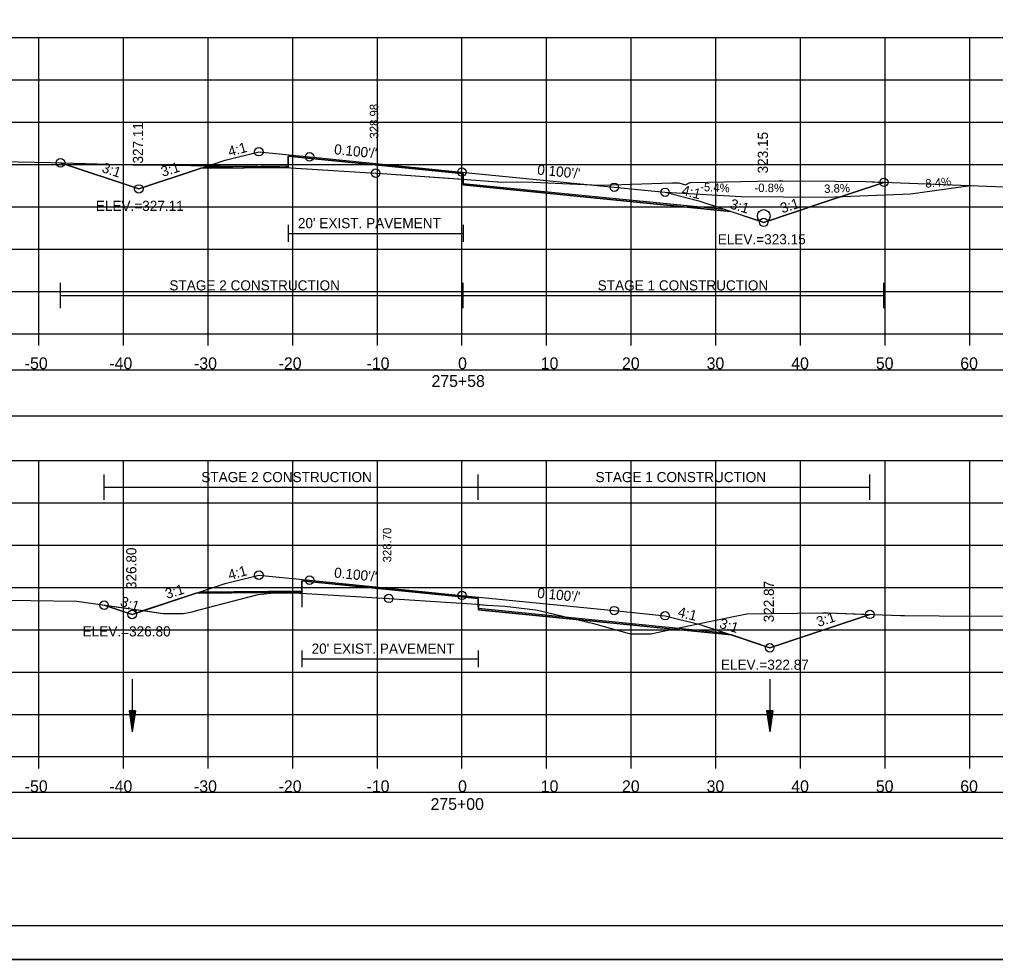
# Model space of a CAD drawing. Extents: x 1376273 to 1384221, y 378927 to 384592.
# Drawn here: x 1380139.4 to 1380254.7, y 383738.6 to 383849.7 of the extents above; entities that cross this region are included whole.
import ezdxf

# ---------------------------------------------------------------- set-up
doc = ezdxf.new("R2010")
doc.units = 0
for name, color, linetype in [('R_Alt Surface', 7, 'Continuous'), ('R_Alt Surface Annot', 7, 'Continuous'), ('R_Axis', 7, 'Continuous'), ('R_Axis Annot', 7, 'Continuous'), ('R_Border', 7, 'Continuous'), ('R_Border Notes', 7, 'Continuous'), ('R_Contours', 7, 'Continuous'), ('R_Dimension', 7, 'Continuous'), ('R_Drive', 7, 'Continuous'), ('R_Exist Surface', 7, 'Continuous'), ('R_Fin Surface', 7, 'Continuous'), ('R_Grid', 7, 'Continuous'), ('R_No Plot', 7, 'Continuous'), ('R_Water', 7, 'Continuous'), ('R_Xsect Elev', 7, 'Continuous'), ('R_Xsect Slope', 7, 'Continuous'), ('T_Detection Zones', 7, 'Continuous')]:
    doc.layers.add(name, color=color, linetype=linetype)

msp = doc.modelspace()

# ---------------------------------------------------------------- linework, layer by layer
at = {"layer": 'R_Alt Surface'}
for points in [[(1380161.32, 383832.29), (1380171.12, 383832.39), (1380171.13, 383833.55), (1380191.66, 383831.5), (1380191.8, 383831.48), (1380191.81, 383830.32), (1380222.68, 383827.26)], [(1380171.13, 383825.42), (1380171.13, 383823.42)], [(1380191.8, 383825.42), (1380191.8, 383823.42)], [(1380171.13, 383824.42), (1380191.8, 383824.42)], [(1380160.77, 383782.06), (1380172.73, 383782.18), (1380172.74, 383783.35), (1380191.66, 383781.46), (1380193.59, 383781.26), (1380193.6, 383780.1), (1380222.79, 383777.18)], [(1380172.74, 383775.12), (1380172.74, 383773.12)], [(1380193.59, 383775.12), (1380193.59, 383773.12)], [(1380172.74, 383774.12), (1380193.59, 383774.12)]]:
    msp.add_lwpolyline(points, dxfattribs=at)
at = {"layer": 'R_Alt Surface Annot'}
msp.add_circle((1380227.31, 383826.47), 0.75, dxfattribs=at)
at = {"layer": 'R_Axis'}
for p, q in [((1380041.66, 383812.56), (1380341.66, 383812.56)), ((1380141.66, 383811.16), (1380141.66, 383812.56)), ((1380151.66, 383811.16), (1380151.66, 383812.56)), ((1380161.66, 383811.16), (1380161.66, 383812.56)), ((1380171.66, 383811.16), (1380171.66, 383812.56)), ((1380181.66, 383811.16), (1380181.66, 383812.56)), ((1380191.66, 383811.16), (1380191.66, 383812.56)), ((1380201.66, 383811.16), (1380201.66, 383812.56)), ((1380211.66, 383811.16), (1380211.66, 383812.56)), ((1380221.66, 383811.16), (1380221.66, 383812.56)), ((1380231.66, 383811.16), (1380231.66, 383812.56)), ((1380241.66, 383811.16), (1380241.66, 383812.56)), ((1380251.66, 383811.16), (1380251.66, 383812.56)), ((1380041.66, 383762.56), (1380341.66, 383762.56)), ((1380141.66, 383761.16), (1380141.66, 383762.56)), ((1380151.66, 383761.16), (1380151.66, 383762.56)), ((1380161.66, 383761.16), (1380161.66, 383762.56)), ((1380171.66, 383761.16), (1380171.66, 383762.56)), ((1380181.66, 383761.16), (1380181.66, 383762.56)), ((1380191.66, 383761.16), (1380191.66, 383762.56)), ((1380201.66, 383761.16), (1380201.66, 383762.56)), ((1380211.66, 383761.16), (1380211.66, 383762.56)), ((1380221.66, 383761.16), (1380221.66, 383762.56)), ((1380231.66, 383761.16), (1380231.66, 383762.56)), ((1380241.66, 383761.16), (1380241.66, 383762.56)), ((1380251.66, 383761.16), (1380251.66, 383762.56))]:
    msp.add_line(p, q, dxfattribs=at)
at = {"layer": 'R_Axis Annot'}
for points in [[(1380040.81, 383802.85), (1380342.5, 383802.85), (1380342.5, 383808.26), (1380040.81, 383808.26)], [(1380040.81, 383752.92), (1380342.5, 383752.92), (1380342.5, 383758.33), (1380040.81, 383758.33)]]:
    msp.add_lwpolyline(points, close=True, dxfattribs=at)
at = {"layer": 'R_Border'}
msp.add_line((1380349.84, 383742.56), (1380033.66, 383742.56), dxfattribs=at)
at = {"layer": 'R_Contours'}
for p, q in [((1380160.25, 383781.89), (1380154.04, 383779.82)), ((1380172.73, 383782.01), (1380160.25, 383781.89)), ((1380172.73, 383782.01), (1380172.73, 383780.22)), ((1380172.73, 383782.01), (1380172.73, 383781.88)), ((1380172.73, 383781.88), (1380172.73, 383782.01)), ((1380193.59, 383780.55), (1380193.59, 383781.26))]:
    msp.add_line(p, q, dxfattribs=at)
for points in [[(1380191.8, 383830.81), (1380192.8, 383830.74), (1380195.83, 383830.5), (1380195.95, 383830.49), (1380196.24, 383830.47), (1380198.2, 383830.49), (1380200.07, 383830.47), (1380207.9, 383830.1), (1380208.14, 383830.1), (1380216.47, 383830.39), (1380217.28, 383830.4), (1380218.09, 383830.17), (1380218.6, 383830.43), (1380218.76, 383830.44), (1380226.57, 383830.6), (1380229.07, 383830.61), (1380229.57, 383830.64), (1380235.79, 383830.59), (1380239.39, 383830.53), (1380241.52, 383830.45), (1380234.24, 383828.03), (1380227.31, 383825.72), (1380223.39, 383827.02), (1380191.81, 383830.15)], [(1380193.59, 383780.55), (1380194.59, 383780.48), (1380196.73, 383780.34), (1380197.04, 383780.31), (1380197.4, 383780.27), (1380200.36, 383779.91), (1380200.93, 383779.78), (1380205.23, 383778.77), (1380193.6, 383779.93)], [(1380216.58, 383777.63), (1380218.64, 383778.05), (1380221.6, 383778.68), (1380225.33, 383779.43), (1380234.31, 383779.56), (1380234.94, 383779.56), (1380239.86, 383779.38), (1380228.02, 383775.43), (1380223.5, 383776.94)], [(1380205.23, 383778.77), (1380207.2, 383778.3), (1380211.15, 383777.2), (1380211.62, 383777.07), (1380212.02, 383777.07), (1380214, 383777.07), (1380214.67, 383777.24), (1380216.58, 383777.63)]]:
    msp.add_lwpolyline(points, close=True, dxfattribs=at)
for points in [[(1380193.59, 383781.26), (1380191.66, 383781.46), (1380172.74, 383783.35), (1380172.73, 383782.01)], [(1380154.04, 383779.82), (1380156.34, 383779.5), (1380157.16, 383779.5), (1380158.73, 383779.5), (1380159.64, 383779.65), (1380160.61, 383779.91), (1380163.32, 383780.62), (1380167.59, 383781.71), (1380169.06, 383781.88), (1380169.65, 383781.93), (1380171.46, 383781.94), (1380171.74, 383781.93), (1380172.73, 383781.88)], [(1380172.73, 383781.88), (1380173.24, 383781.85), (1380183.01, 383781.27), (1380193.4, 383780.57), (1380193.59, 383780.55)]]:
    msp.add_lwpolyline(points, dxfattribs=at)
at = {"layer": 'R_Dimension'}
for p, q in [((1380144.22, 383815.57), (1380144.22, 383818.57)), ((1380191.8, 383815.57), (1380191.8, 383818.57)), ((1380241.52, 383815.57), (1380241.52, 383818.57)), ((1380144.22, 383817.07), (1380241.52, 383817.07)), ((1380149.37, 383792.91), (1380149.37, 383795.91)), ((1380193.59, 383792.91), (1380193.59, 383795.91)), ((1380239.86, 383792.91), (1380239.86, 383795.91)), ((1380149.37, 383794.41), (1380239.86, 383794.41))]:
    msp.add_line(p, q, dxfattribs=at)
at = {"layer": 'R_Drive'}
for p, q in [((1380215.66, 383829.27), (1380224.64, 383828.78)), ((1380234.64, 383828.71), (1380244.64, 383829.09)), ((1380244.64, 383829.09), (1380251.75, 383830.07)), ((1380224.64, 383828.78), (1380234.64, 383828.71))]:
    msp.add_line(p, q, dxfattribs=at)
at = {"layer": 'R_Exist Surface'}
for points in [[(1380137.27, 383832.91), (1380143.13, 383832.78), (1380145.76, 383832.73), (1380152.78, 383832.51), (1380163.09, 383832.39), (1380167.53, 383832.37), (1380169.64, 383832.28), (1380170.13, 383832.26), (1380180.23, 383831.63), (1380181.47, 383831.54), (1380182.79, 383831.45), (1380192.8, 383830.74), (1380195.83, 383830.5), (1380195.95, 383830.49), (1380196.24, 383830.47), (1380198.2, 383830.49), (1380200.07, 383830.47), (1380207.9, 383830.1), (1380208.14, 383830.1), (1380216.47, 383830.39), (1380217.28, 383830.4), (1380218.09, 383830.17), (1380218.6, 383830.43), (1380218.76, 383830.44), (1380226.57, 383830.6), (1380229.07, 383830.61), (1380229.57, 383830.64), (1380235.79, 383830.59), (1380239.39, 383830.53), (1380254.7, 383829.95), (1380257.77, 383829.89)], [(1380137.13, 383781.05), (1380140.68, 383781.03), (1380146.17, 383780.93), (1380153.09, 383779.95), (1380156.34, 383779.5), (1380157.16, 383779.5), (1380158.73, 383779.5), (1380159.64, 383779.65), (1380160.61, 383779.91), (1380163.32, 383780.62), (1380167.59, 383781.71), (1380169.06, 383781.88), (1380169.65, 383781.93), (1380171.46, 383781.94), (1380171.74, 383781.93), (1380173.24, 383781.85), (1380183.01, 383781.27), (1380193.4, 383780.57), (1380194.59, 383780.48), (1380196.73, 383780.34), (1380197.04, 383780.31), (1380197.4, 383780.27), (1380200.36, 383779.91), (1380200.93, 383779.78), (1380207.2, 383778.3), (1380211.15, 383777.2), (1380211.62, 383777.07), (1380212.02, 383777.07), (1380214, 383777.07), (1380214.67, 383777.24), (1380218.64, 383778.05), (1380221.6, 383778.68), (1380225.33, 383779.43), (1380234.31, 383779.56), (1380234.94, 383779.56), (1380243.46, 383779.24), (1380243.95, 383779.23), (1380248.05, 383779.2), (1380268.33, 383779.12)]]:
    msp.add_lwpolyline(points, dxfattribs=at)
at = {"layer": 'R_Fin Surface'}
for points in [[(1380144.22, 383832.76), (1380153.48, 383829.67), (1380160.48, 383832.01), (1380163.66, 383833.07), (1380167.66, 383834.07), (1380173.66, 383833.47), (1380191.66, 383831.67), (1380209.66, 383829.87), (1380215.66, 383829.27), (1380219.66, 383828.27), (1380222.39, 383827.36), (1380227.31, 383825.72), (1380234.24, 383828.03), (1380241.52, 383830.45)], [(1380149.37, 383780.47), (1380152.69, 383779.37), (1380160.48, 383781.96), (1380163.66, 383783.02), (1380167.66, 383784.02), (1380173.66, 383783.42), (1380191.66, 383781.62), (1380209.66, 383779.82), (1380215.66, 383779.22), (1380219.66, 383778.22), (1380222.63, 383777.23), (1380228.02, 383775.43), (1380239.86, 383779.38)]]:
    msp.add_lwpolyline(points, dxfattribs=at)
at = {"layer": 'R_Grid'}
for p, q in [((1380041.66, 383847.56), (1380341.66, 383847.56)), ((1380141.66, 383812.56), (1380141.66, 383847.56)), ((1380151.66, 383812.56), (1380151.66, 383847.56)), ((1380161.66, 383812.56), (1380161.66, 383847.56)), ((1380171.66, 383812.56), (1380171.66, 383847.56)), ((1380181.66, 383812.56), (1380181.66, 383847.56)), ((1380191.66, 383812.56), (1380191.66, 383847.56)), ((1380201.66, 383812.56), (1380201.66, 383847.56)), ((1380211.66, 383812.56), (1380211.66, 383847.56)), ((1380221.66, 383812.56), (1380221.66, 383847.56)), ((1380231.66, 383812.56), (1380231.66, 383847.56)), ((1380241.66, 383812.56), (1380241.66, 383847.56)), ((1380251.66, 383812.56), (1380251.66, 383847.56)), ((1380041.66, 383842.56), (1380341.66, 383842.56)), ((1380041.66, 383837.56), (1380341.66, 383837.56)), ((1380041.66, 383832.56), (1380341.66, 383832.56)), ((1380041.66, 383827.56), (1380341.66, 383827.56)), ((1380041.66, 383822.56), (1380341.66, 383822.56)), ((1380041.66, 383817.56), (1380341.66, 383817.56)), ((1380041.66, 383812.56), (1380341.66, 383812.56)), ((1380041.66, 383797.56), (1380341.66, 383797.56)), ((1380141.66, 383762.56), (1380141.66, 383797.56)), ((1380151.66, 383762.56), (1380151.66, 383797.56)), ((1380161.66, 383762.56), (1380161.66, 383797.56)), ((1380171.66, 383762.56), (1380171.66, 383797.56)), ((1380181.66, 383762.56), (1380181.66, 383797.56)), ((1380191.66, 383762.56), (1380191.66, 383797.56)), ((1380201.66, 383762.56), (1380201.66, 383797.56)), ((1380211.66, 383762.56), (1380211.66, 383797.56)), ((1380221.66, 383762.56), (1380221.66, 383797.56)), ((1380231.66, 383762.56), (1380231.66, 383797.56)), ((1380241.66, 383762.56), (1380241.66, 383797.56)), ((1380251.66, 383762.56), (1380251.66, 383797.56)), ((1380041.66, 383792.56), (1380341.66, 383792.56)), ((1380041.66, 383787.56), (1380341.66, 383787.56)), ((1380041.66, 383782.56), (1380341.66, 383782.56)), ((1380041.66, 383777.56), (1380341.66, 383777.56)), ((1380041.66, 383772.56), (1380341.66, 383772.56)), ((1380041.66, 383767.56), (1380341.66, 383767.56)), ((1380041.66, 383762.56), (1380341.66, 383762.56))]:
    msp.add_line(p, q, dxfattribs=at)
at = {"layer": 'R_No Plot'}
msp.add_line((1380021.26, 383738.59), (1380354.59, 383738.59), dxfattribs=at)
for points in [[(1380021.25, 383951.92), (1380354.59, 383951.92), (1380354.59, 383738.58), (1380021.25, 383738.58)], [(1380267.58, 383948.02), (1380267.58, 383938.14), (1380303.31, 383938.14), (1380303.31, 383935.22), (1380326.51, 383935.22), (1380326.51, 383910.89), (1380349.84, 383910.89), (1380349.84, 383742.56), (1380033.66, 383742.56), (1380033.66, 383948.02)]]:
    msp.add_lwpolyline(points, close=True, dxfattribs=at)
for points in [[(1380160.8, 383832.11), (1380171.12, 383832.22), (1380171.13, 383833.55), (1380191.66, 383831.5), (1380191.8, 383831.48), (1380191.81, 383830.15), (1380223.39, 383827.02)], [(1380160.25, 383781.89), (1380172.73, 383782.01), (1380172.74, 383783.35), (1380191.66, 383781.46), (1380193.59, 383781.26), (1380193.6, 383779.93), (1380223.5, 383776.94)]]:
    msp.add_lwpolyline(points, dxfattribs=at)
for centre in [(1380167.66, 383834.07), (1380173.66, 383833.47), (1380144.22, 383832.76), (1380181.47, 383831.54), (1380191.66, 383831.67), (1380209.66, 383829.87), (1380241.52, 383830.45), (1380153.48, 383829.67), (1380153.48, 383829.67), (1380215.66, 383829.27), (1380227.31, 383825.72), (1380227.31, 383825.72), (1380167.66, 383784.02), (1380173.66, 383783.42), (1380191.66, 383781.62), (1380149.37, 383780.47), (1380183.01, 383781.27), (1380152.69, 383779.37), (1380152.69, 383779.37), (1380209.66, 383779.82), (1380215.66, 383779.22), (1380239.86, 383779.38), (1380228.02, 383775.43), (1380228.02, 383775.43)]:
    msp.add_circle(centre, 0.5, dxfattribs=at)
at = {"layer": 'R_Water'}
for p, q in [((1380152.69, 383771.73), (1380152.69, 383765.48)), ((1380228.02, 383771.73), (1380228.02, 383765.48)), ((1380152.32, 383767.98), (1380152.69, 383765.48)), ((1380153.07, 383767.98), (1380152.32, 383767.98)), ((1380152.38, 383767.98), (1380152.69, 383765.9)), ((1380152.44, 383767.98), (1380152.69, 383766.33)), ((1380152.51, 383767.98), (1380152.69, 383766.74)), ((1380152.57, 383767.98), (1380152.69, 383767.17)), ((1380152.63, 383767.98), (1380152.69, 383767.59)), ((1380153.07, 383767.98), (1380152.69, 383765.48)), ((1380152.81, 383767.98), (1380152.69, 383767.17)), ((1380152.94, 383767.98), (1380152.69, 383766.33)), ((1380153, 383767.98), (1380152.69, 383765.9)), ((1380152.88, 383767.98), (1380152.69, 383766.74)), ((1380152.75, 383767.98), (1380152.69, 383767.59)), ((1380227.65, 383767.98), (1380228.02, 383765.48)), ((1380228.4, 383767.98), (1380227.65, 383767.98)), ((1380227.71, 383767.98), (1380228.02, 383765.9)), ((1380227.78, 383767.98), (1380228.02, 383766.33)), ((1380227.84, 383767.98), (1380228.02, 383766.74)), ((1380227.9, 383767.98), (1380228.02, 383767.17)), ((1380227.97, 383767.98), (1380228.02, 383767.59)), ((1380228.4, 383767.98), (1380228.02, 383765.48)), ((1380228.15, 383767.98), (1380228.02, 383767.17)), ((1380228.27, 383767.98), (1380228.02, 383766.33)), ((1380228.34, 383767.98), (1380228.02, 383765.9)), ((1380228.21, 383767.98), (1380228.02, 383766.74)), ((1380228.08, 383767.98), (1380228.02, 383767.59))]:
    msp.add_line(p, q, dxfattribs=at)
at = {"layer": 'T_Detection Zones'}
for points in [[(1380144.22, 383832.76), (1380145.76, 383832.73), (1380152.78, 383832.51), (1380163.09, 383832.39), (1380167.53, 383832.37), (1380169.64, 383832.28), (1380170.13, 383832.26), (1380170.8, 383832.22), (1380160.8, 383832.11), (1380160.48, 383832.01), (1380153.48, 383829.67)], [(1380170.8, 383832.22), (1380180.23, 383831.63), (1380181.47, 383831.54), (1380182.79, 383831.45), (1380191.8, 383830.81), (1380191.8, 383831.48), (1380191.66, 383831.5), (1380171.13, 383833.55), (1380171.12, 383832.22)], [(1380149.37, 383780.47), (1380153.09, 383779.95), (1380154.04, 383779.82), (1380152.69, 383779.37)]]:
    msp.add_lwpolyline(points, close=True, dxfattribs=at)

# ---------------------------------------------------------------- texts
at = {"layer": 'R_Alt Surface'}
for p in [(1380172.27, 383825.03), (1380173.89, 383774.73)]:
    msp.add_text("20' EXIST. PAVEMENT", height=1.2, dxfattribs=at).set_placement(p)
at = {"layer": 'R_Axis Annot'}
for s, p in [('-50', (1380140, 383808.36)), ('-40', (1380150, 383808.36)), ('-30', (1380160, 383808.36)), ('-20', (1380170, 383808.36)), ('-10', (1380180.39, 383808.36)), ('0', (1380191.2, 383808.36)), ('10', (1380200.97, 383808.36)), ('20', (1380210.57, 383808.36)), ('30', (1380220.57, 383808.36)), ('40', (1380230.57, 383808.36)), ('50', (1380240.57, 383808.36)), ('60', (1380250.54, 383808.36)), ('275+58', (1380188.06, 383806.26)), ('-50', (1380140, 383758.36)), ('-40', (1380150, 383758.36)), ('-30', (1380160, 383758.36)), ('-20', (1380170, 383758.36)), ('-10', (1380180.39, 383758.36)), ('0', (1380191.2, 383758.36)), ('10', (1380200.97, 383758.36)), ('20', (1380210.57, 383758.36)), ('30', (1380220.57, 383758.36)), ('40', (1380230.57, 383758.36)), ('50', (1380240.57, 383758.36)), ('60', (1380250.54, 383758.36)), ('275+00', (1380187.95, 383756.26))]:
    msp.add_text(s, height=1.4, dxfattribs=at).set_placement(p)
at = {"layer": 'R_Border Notes'}
for s, p in [('ELEV.=327.11', (1380148.39, 383827.07)), ('ELEV.=323.15', (1380221.88, 383823.12)), ('ELEV.=326.80', (1380146.84, 383776.77)), ('ELEV.=322.87', (1380222.25, 383772.83))]:
    msp.add_text(s, height=1.2, dxfattribs=at).set_placement(p)
at = {"layer": 'R_Dimension'}
for s, p in [('STAGE 2 CONSTRUCTION', (1380157.09, 383817.67)), ('STAGE 1 CONSTRUCTION', (1380207.7, 383817.67)), ('STAGE 2 CONSTRUCTION', (1380160.86, 383795.01)), ('STAGE 1 CONSTRUCTION', (1380207.44, 383795.01))]:
    msp.add_text(s, height=1.2, dxfattribs=at).set_placement(p)
at = {"layer": 'R_Drive'}
for s, rotation, p in [('-5.4%', 356.9234, (1380219.78, 383829.44)), ('-0.8%', 359.5574, (1380226.22, 383829.31)), ('3.8%', 2.1914, (1380234.47, 383829.18)), ('8.4%', 4.8254, (1380246.45, 383829.81))]:
    msp.add_text(s, height=1, rotation=rotation, dxfattribs=at).set_placement(p)
at = {"layer": 'R_Xsect Elev'}
for s, height, p in [('328.98', 1, (1380181.77, 383835.63)), ('327.11', 1.2, (1380153.98, 383832.67)), ('323.15', 1.2, (1380227.81, 383831.5)), ('328.70', 1, (1380183.31, 383785.53)), ('326.80', 1.2, (1380153.19, 383782.37)), ('322.87', 1.2, (1380228.52, 383778.43))]:
    msp.add_text(s, height=height, rotation=90, dxfattribs=at).set_placement(p)
at = {"layer": 'R_Xsect Slope'}
for s, rotation, p in [('4:1', 15.5158, (1380164.21, 383833.47)), ("0.100'/'", 354.2894, (1380176.51, 383833.78)), ('3:1', 341.5651, (1380149.01, 383831.69)), ('3:1', 17.214, (1380156.3, 383831.09)), ("0.100'/'", 354.2894, (1380200.51, 383831.38)), ('4:1', 345.9638, (1380217.54, 383828.98)), ('3:1', 343.0527, (1380223.24, 383827.39)), ('3:1', 18.4349, (1380229.51, 383826.77)), ('4:1', 15.5158, (1380164.21, 383783.43)), ("0.100'/'", 354.2894, (1380176.51, 383783.74)), ('3:1', 17.2788, (1380156.81, 383781.19)), ("0.100'/'", 354.2894, (1380200.51, 383781.34)), ('3:1', 341.5651, (1380151.19, 383780.4)), ('4:1', 345.9638, (1380217.08, 383779.14)), ('3:1', 18.4349, (1380233.78, 383777.88)), ('3:1', 342.9659, (1380221.99, 383777.81))]:
    msp.add_text(s, height=1.2, rotation=rotation, dxfattribs=at).set_placement(p)

doc.saveas('drawing.dxf')
